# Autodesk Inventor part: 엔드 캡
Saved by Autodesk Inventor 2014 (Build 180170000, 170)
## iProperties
Created: 2026-04
Part Number: 엔드 캡
Material: 강철, 연강
Document SubType Name: Modeling
Designer: dg
Density: 7.86 g/cm^3
Appearance: 강철
Author: jhkim
Creation Date: 2026-03-27
Sending System: Autodesk Inventor 2026
Preprocessor: ST-DEVELOPER v20.1
Author: dg
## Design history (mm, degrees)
node "엔드 캡1"
node "솔리드1"
node "기준1"
